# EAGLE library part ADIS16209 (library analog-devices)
High Accuracy, Dual-Axis Digital Inclinometer and Accelerometer Source: http://www.analog.com/static/imported-files/data_sheets/ADIS16209.pdf
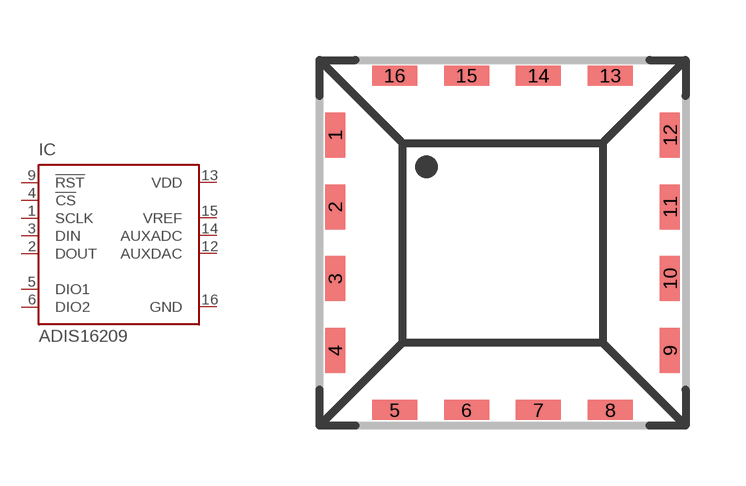
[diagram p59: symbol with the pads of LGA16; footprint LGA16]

Designator prefix IC

## ADIS16209 (MPN: ADIS16209CCCZ; OC_FARNELL: 1607244; OC_NEWARK: 71M1609)  [LGA16]
1  SCLK  in
2  DOUT  out
3  DIN  in
4  !CS  in
5  DIO1
6  DIO2
9  !RST  in
12  AUXDAC  in
13  VDD  pwr
14  AUXADC  in
15  VREF  in
16  GND  pwr

## Footprint LGA16 (pad centres in mm)
16-Terminal Land Grid Array [LGA] (CC-16-2) Source: http://www.analog.com/static/imported-files/data_sheets/ADIS16209.pdf
smd 0.5 x 1.127: 1 -4.186,2.696; 2 -4.187,0.898; 3 -4.187,-0.898; 4 -4.187,-2.696; 9 4.186,-2.696; 10 4.187,-0.898; 11 4.187,0.898; 12 4.187,2.696
smd 1.127 x 0.5: 5 -2.696,-4.186; 6 -0.898,-4.187; 7 0.898,-4.187; 8 2.696,-4.187; 13 2.696,4.186; 14 0.898,4.187; 15 -0.898,4.187; 16 -2.696,4.187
